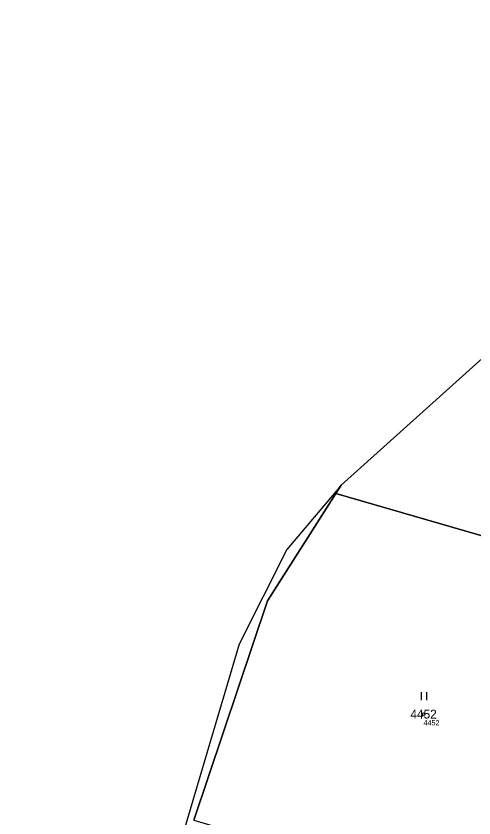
# Model space of a CAD drawing. Extents: x -739214 to -733252, y -1147612 to -1142842.
# Drawn here: x -737816.9 to -737729.2, y -1145120.5 to -1144967 of the extents above; entities that cross this region are included whole.
import ezdxf

# ---------------------------------------------------------------- set-up
doc = ezdxf.new("R2010")
doc.units = 0
for name, color, linetype in [('Definiční body', 7, 'Continuous'), ('Hranice parcel', 7, 'Continuous'), ('Parcelní čísla', 7, 'Continuous'), ('Polygon ku', 7, 'Continuous'), ('Polygon parcely', 7, 'Continuous'), ('Značky kultur', 7, 'Continuous')]:
    doc.layers.add(name, color=color, linetype=linetype)

msp = doc.modelspace()

# ---------------------------------------------------------------- linework, layer by layer
at = {"layer": 'Definiční body'}
msp.add_circle((-737738.86, -1145100.64), 0.25, dxfattribs=at)
at = {"layer": 'Hranice parcel'}
for p, q in [((-737726.97, -1145031.96), (-737754.64, -1145056.79)), ((-737754.64, -1145056.79), (-737755.66, -1145058.39)), ((-737755.66, -1145058.39), (-737696.05, -1145075.66))]:
    msp.add_line(p, q, dxfattribs=at)
for points in [[(-737754.64, -1145056.79), (-737755.88, -1145058.32), (-737765.05, -1145069.11), (-737774.19, -1145087.23), (-737780.38, -1145108.12)], [(-737755.66, -1145058.39), (-737768.72, -1145078.98), (-737782.83, -1145120.95)], [(-737780.38, -1145108.12), (-737805.81, -1145193.98), (-737816.92, -1145233.66)]]:
    msp.add_lwpolyline(points, dxfattribs=at)
at = {"layer": 'Polygon ku'}
msp.add_lwpolyline([(-737717.82, -1144965.83), (-737709.83, -1144968.83), (-737690.77, -1144973.31), (-737689.97, -1144973.5), (-737679.92, -1144975.51), (-737678.59, -1144975.78), (-737678.19, -1144976.23), (-737674.82, -1144980.15), (-737672.86, -1144982.43), (-737682.69, -1144991.77), (-737691.33, -1144999.98), (-737726.97, -1145031.96), (-737754.64, -1145056.79), (-737755.88, -1145058.32), (-737765.05, -1145069.11), (-737774.19, -1145087.23), (-737780.38, -1145108.12), (-737805.81, -1145193.98)], dxfattribs=at)
at = {"layer": 'Polygon parcely'}
for points in [[(-737683.64, -1145044.59), (-737726.97, -1145031.96), (-737754.64, -1145056.79), (-737755.66, -1145058.39), (-737696.05, -1145075.66)], [(-737696.05, -1145075.66), (-737755.66, -1145058.39), (-737768.72, -1145078.98), (-737782.83, -1145120.95), (-737721.37, -1145139.05)]]:
    msp.add_lwpolyline(points, close=True, dxfattribs=at)
msp.add_lwpolyline([(-737782.83, -1145120.95), (-737768.72, -1145078.98), (-737755.66, -1145058.39), (-737754.64, -1145056.79), (-737755.88, -1145058.32), (-737765.05, -1145069.11), (-737774.19, -1145087.23), (-737780.38, -1145108.12), (-737805.81, -1145193.98)], dxfattribs=at)
at = {"layer": 'Značky kultur'}
for p, q in [((-737739.24, -1145097.95), (-737739.24, -1145096.45)), ((-737738.24, -1145097.95), (-737738.24, -1145096.45))]:
    msp.add_line(p, q, dxfattribs=at)

# ---------------------------------------------------------------- texts
at = {"layer": 'Definiční body'}
msp.add_text('4452', height=1, dxfattribs=at).set_placement((-737738.86, -1145102.8))
at = {"layer": 'Parcelní čísla'}
msp.add_text('4452', height=1.7, dxfattribs=at).set_placement((-737741.37, -1145101.49))

doc.saveas('drawing.dxf')
